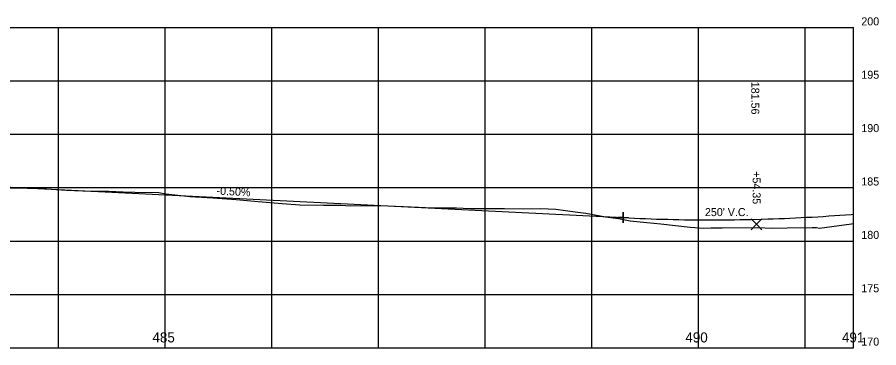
# Model space of a CAD drawing. Extents: x 7585489 to 7587427, y 550013 to 552072.
# Drawn here: x 7586620 to 7587427, y 550954 to 551264 of the extents above; entities that cross this region are included whole.
import ezdxf

# ---------------------------------------------------------------- set-up
doc = ezdxf.new("R2010")
doc.units = 0
for name, color, linetype in [('E_RDWY_PROF_Ground', 7, 'Continuous'), ('P_RDWY_PROF_Align', 7, 'Continuous'), ('P_RDWY_PROF_AlignTx', 7, 'Continuous'), ('P_RDWY_PROF_Grid', 7, 'Continuous'), ('P_RDWY_PROF_GridTx', 7, 'Continuous')]:
    doc.layers.add(name, color=color, linetype=linetype)

msp = doc.modelspace()

# ---------------------------------------------------------------- linework, layer by layer
msp.add_lwpolyline([(7587187.7, 551076.12), (7587187.7, 551081.12), (7587187.7, 551076.12), (7587182.7, 551076.12), (7587187.7, 551076.12), (7587187.7, 551071.12), (7587187.7, 551076.12), (7587192.7, 551076.12)])
at = {"layer": 'E_RDWY_PROF_Ground'}
msp.add_lwpolyline([(7586606.93, 551104.14), (7586629.2, 551103.88), (7586642.5, 551103.44), (7586651.68, 551102.78), (7586665.87, 551101.9), (7586688.46, 551101.05), (7586705.51, 551100.87), (7586718.79, 551100.18), (7586729.85, 551100.1), (7586752.37, 551099.61), (7586758.89, 551098.38), (7586781.39, 551096.09), (7586802.75, 551094.83), (7586824.93, 551093.18), (7586845.38, 551091.34), (7586867.9, 551089.3), (7586884.36, 551088.18), (7586906.78, 551087.96), (7586922.77, 551087.87), (7586932.22, 551087.26), (7586946.44, 551087.39), (7586959.3, 551087.66), (7586966.95, 551087.23), (7586988.94, 551086.23), (7587009.28, 551085.48), (7587031.27, 551085.44), (7587043.87, 551084.71), (7587061.2, 551084.62), (7587061.75, 551084.65), (7587076.32, 551084.73), (7587094.42, 551084.4), (7587109.93, 551084.61), (7587124.49, 551083.99), (7587142.51, 551081.63), (7587152.73, 551080.46), (7587170.88, 551076.96), (7587183.27, 551075.24), (7587194.13, 551073.19), (7587209.62, 551071.53), (7587222.93, 551070.33), (7587250.44, 551067.07), (7587263.15, 551066.35), (7587269.87, 551066.61), (7587280.32, 551066.6), (7587313.48, 551066.76), (7587327.71, 551066.18), (7587341.17, 551066.65), (7587364.91, 551067.05), (7587368.9, 551066.87), (7587371.48, 551066.32), (7587401.51, 551070.48), (7587403.04, 551070.75), (7587403.35, 551070.99)], dxfattribs=at)
at = {"layer": 'P_RDWY_PROF_Align'}
msp.add_line((7586466.85, 551112.16), (7587187.7, 551076.12), dxfattribs=at)
for points in [[(7587187.7, 551076.12), (7587192.91, 551075.87), (7587198.12, 551075.63), (7587203.33, 551075.41), (7587208.54, 551075.21), (7587213.75, 551075.02), (7587218.95, 551074.85), (7587224.16, 551074.7), (7587229.37, 551074.56), (7587234.58, 551074.44), (7587239.79, 551074.33), (7587245, 551074.24), (7587250.2, 551074.17), (7587255.41, 551074.12), (7587260.62, 551074.08), (7587265.83, 551074.05), (7587271.04, 551074.05), (7587276.25, 551074.06), (7587281.45, 551074.08), (7587286.66, 551074.13), (7587291.87, 551074.18), (7587297.08, 551074.26), (7587302.29, 551074.35), (7587307.5, 551074.46), (7587317.91, 551074.72), (7587323.12, 551074.88), (7587328.33, 551075.05), (7587333.54, 551075.24), (7587338.75, 551075.45), (7587343.95, 551075.67), (7587349.16, 551075.91), (7587354.37, 551076.17), (7587359.58, 551076.44), (7587364.79, 551076.73), (7587370, 551077.03), (7587375.2, 551077.35), (7587380.41, 551077.69), (7587385.62, 551078.04), (7587390.83, 551078.41), (7587396.04, 551078.8), (7587401.25, 551079.2), (7587403.35, 551079.37)], [(7587312.7, 551069.87), (7587307.7, 551074.87), (7587312.7, 551069.87), (7587307.7, 551064.87), (7587312.7, 551069.87), (7587317.7, 551064.87), (7587312.7, 551069.87), (7587317.7, 551074.87)]]:
    msp.add_lwpolyline(points, dxfattribs=at)
at = {"layer": 'P_RDWY_PROF_Grid'}
for p, q in [((7585558.35, 551254.25), (7587403.35, 551254.25)), ((7585558.35, 551254.25), (7587403.35, 551254.25)), ((7586658.35, 550954.25), (7586658.35, 551254.25)), ((7586758.35, 550954.25), (7586758.35, 551254.25)), ((7586858.35, 550954.25), (7586858.35, 551254.25)), ((7586958.35, 550954.25), (7586958.35, 551254.25)), ((7587058.35, 550954.25), (7587058.35, 551254.25)), ((7587158.35, 550954.25), (7587158.35, 551254.25)), ((7587258.35, 550954.25), (7587258.35, 551254.25)), ((7587358.35, 550954.25), (7587358.35, 551254.25)), ((7587403.35, 550954.25), (7587403.35, 551254.25)), ((7585558.35, 551204.25), (7587403.35, 551204.25)), ((7585558.35, 551154.25), (7587403.35, 551154.25)), ((7585558.35, 551104.25), (7587403.35, 551104.25)), ((7585558.35, 551054.25), (7587403.35, 551054.25)), ((7585558.35, 551004.25), (7587403.35, 551004.25)), ((7585558.35, 550954.25), (7587403.35, 550954.25))]:
    msp.add_line(p, q, dxfattribs=at)
at = {"layer": 'P_RDWY_PROF_GridTx'}
for p, q in [((7586658.35, 550954.25), (7586658.35, 550964.25)), ((7586858.35, 550954.25), (7586858.35, 550964.25)), ((7586958.35, 550954.25), (7586958.35, 550964.25)), ((7587058.35, 550954.25), (7587058.35, 550964.25)), ((7587158.35, 550954.25), (7587158.35, 550964.25)), ((7587358.35, 550954.25), (7587358.35, 550964.25))]:
    msp.add_line(p, q, dxfattribs=at)

# ---------------------------------------------------------------- texts
at = {"layer": 'P_RDWY_PROF_AlignTx'}
for s, rotation, p in [('181.56                              ', 270, (7587307.7, 551203.45)), ('                              +54.35', 270, (7587308.95, 551203.24)), ('-0.50%', 357.13759, (7586806.23, 551097.7))]:
    msp.add_text(s, height=7.5, rotation=rotation, dxfattribs=at).set_placement(p)
msp.add_text("250' V.C.", height=7.5, dxfattribs=at).set_placement((7587264.2, 551077.58))
at = {"layer": 'P_RDWY_PROF_GridTx'}
for s, height, p in [('200', 7.5, (7587410.85, 551256.25)), ('200', 7.5, (7587410.85, 551256.25)), ('195', 7.5, (7587410.85, 551206.25)), ('190', 7.5, (7587410.85, 551156.25)), ('185', 7.5, (7587410.85, 551106.25)), ('180', 7.5, (7587410.85, 551056.25)), ('175', 7.5, (7587410.85, 551006.25)), ('485', 9.4, (7586746.29, 550959.25)), ('490', 9.4, (7587245.88, 550959.25)), ('491', 9.4, (7587392.66, 550959.25)), ('170', 7.5, (7587410.85, 550956.25))]:
    msp.add_text(s, height=height, dxfattribs=at).set_placement(p)

doc.saveas('drawing.dxf')
